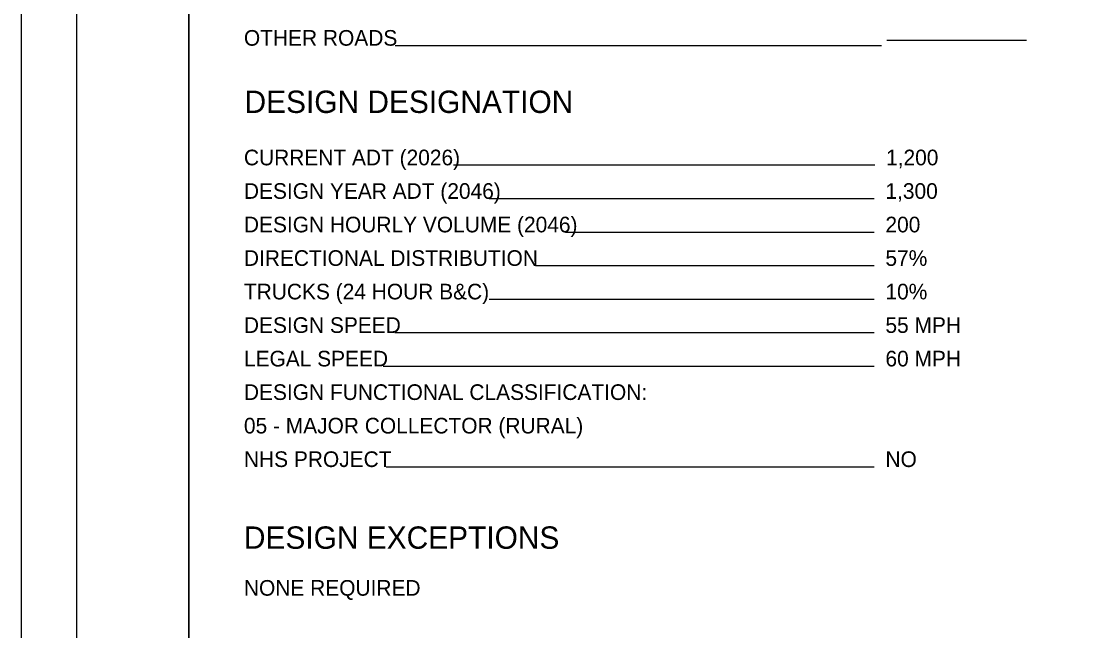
# Model space of a CAD drawing. Extents: x -19.9 to 41.9, y 0 to 32.3.
# Drawn here: x 0 to 9.45, y 5.64 to 11.1 of the extents above; entities that cross this region are included whole.
import ezdxf

# ---------------------------------------------------------------- set-up
doc = ezdxf.new("R2010")
doc.units = 0
for name, color, linetype in [('SH_Border', 7, 'Continuous'), ('SH_Cut_Line', 7, 'Continuous'), ('SH_Data', 7, 'Continuous'), ('SH_Text', 7, 'Continuous')]:
    doc.layers.add(name, color=color, linetype=linetype)

msp = doc.modelspace()

# ---------------------------------------------------------------- linework, layer by layer
at = {"layer": 'SH_Border'}
for points in [[(0.5, 21.5), (1.5, 21.5), (1.5, 0.5), (0.5, 0.5)], [(1.5, 21.5), (33.5, 21.5), (33.5, 0.5), (1.5, 0.5)]]:
    msp.add_lwpolyline(points, close=True, dxfattribs=at)
at = {"layer": 'SH_Cut_Line'}
msp.add_lwpolyline([(0, 0), (34, 0), (34, 22), (0, 22)], close=True, dxfattribs=at)
at = {"layer": 'SH_Data'}
for p, q in [((7.7, 10.8767), (3.3471, 10.8767)), ((9, 10.9223), (7.75, 10.9223)), ((7.6424, 9.8062), (3.871, 9.8062)), ((7.6368, 9.5062), (4.1885, 9.5062)), ((7.6368, 9.2062), (4.8723, 9.2062)), ((7.6368, 8.9062), (4.6037, 8.9062)), ((7.6368, 8.6062), (4.1885, 8.6062)), ((7.6368, 8.3062), (3.346, 8.3062)), ((7.6368, 8.0062), (3.2422, 8.0062)), ((7.6368, 7.1062), (3.2669, 7.1062))]:
    msp.add_line(p, q, dxfattribs=at)

# ---------------------------------------------------------------- texts
msp.add_text('DESIGN DESIGNATION', height=0.2, dxfattribs=at).set_placement((2, 10.2747))
at = {"layer": 'SH_Text'}
for s, height, p in [('OTHER ROADS', 0.14, (1.9944, 10.8767)), ('CURRENT ADT (2026)', 0.14, (1.9944, 9.8062)), ('1,200', 0.14, (7.7424, 9.8062)), ('DESIGN YEAR ADT (2046)', 0.14, (1.9944, 9.5062)), ('1,300', 0.14, (7.7368, 9.5062)), ('DESIGN HOURLY VOLUME (2046)', 0.14, (1.9944, 9.2062)), ('200', 0.14, (7.7368, 9.2062)), ('DIRECTIONAL DISTRIBUTION', 0.14, (1.9944, 8.9062)), ('57%', 0.14, (7.7368, 8.9062)), ('TRUCKS (24 HOUR B&C)', 0.14, (1.9944, 8.6062)), ('10%', 0.14, (7.7368, 8.6062)), ('DESIGN SPEED', 0.14, (1.9944, 8.3062)), ('55 MPH', 0.14, (7.7368, 8.3062)), ('LEGAL SPEED', 0.14, (1.9944, 8.0062)), ('60 MPH', 0.14, (7.7368, 8.0062)), ('DESIGN FUNCTIONAL CLASSIFICATION:', 0.14, (1.9944, 7.7062)), ('05 - MAJOR COLLECTOR (RURAL)', 0.14, (1.9944, 7.4062)), ('NHS PROJECT', 0.14, (1.9944, 7.1062)), ('NO', 0.14, (7.7368, 7.1062)), ('DESIGN EXCEPTIONS', 0.2, (1.9944, 6.3744)), ('NONE REQUIRED', 0.14, (1.9944, 5.9544))]:
    msp.add_text(s, height=height, dxfattribs=at).set_placement(p)

doc.saveas('drawing.dxf')
